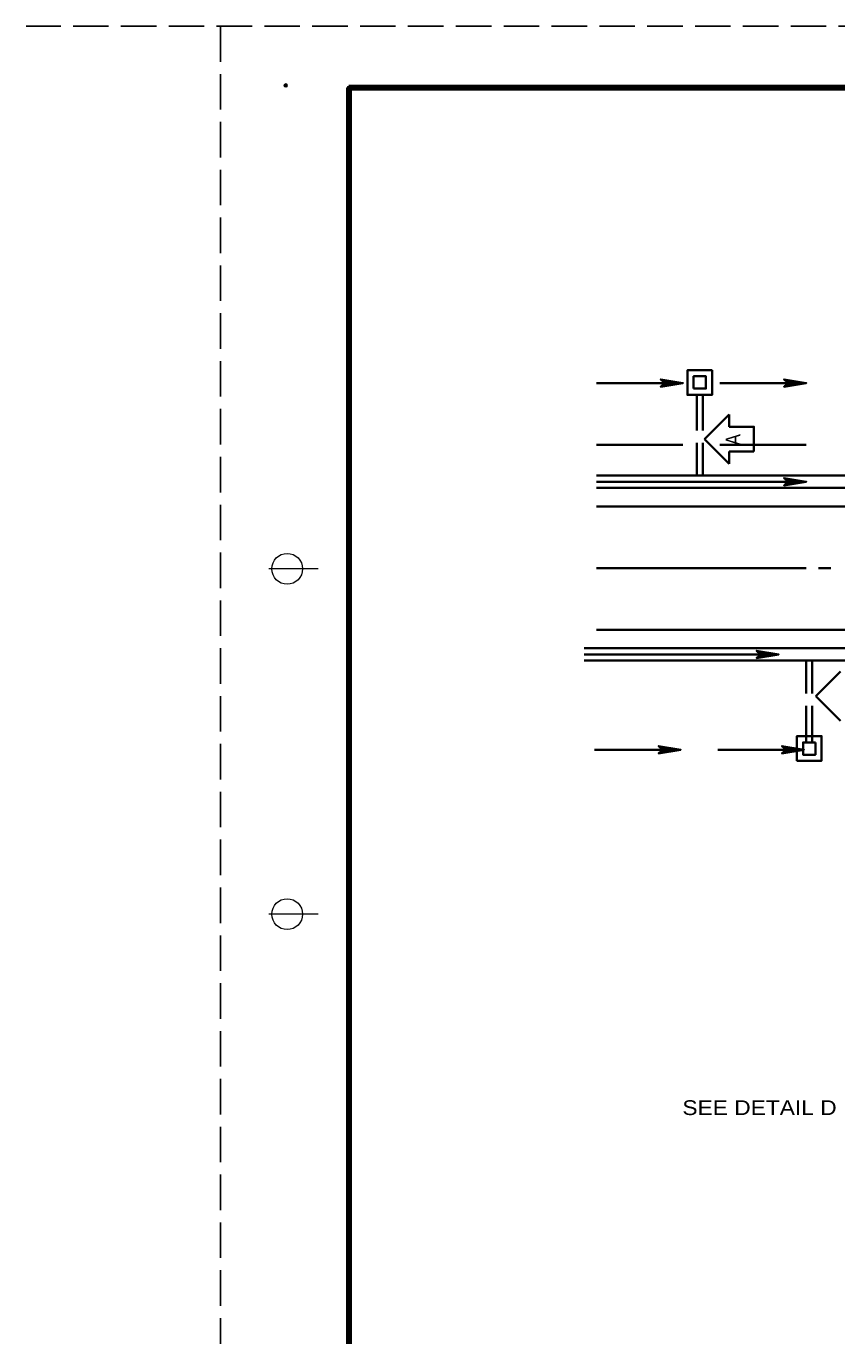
# Model space of a CAD drawing. Extents: x -48732 to -48696.6, y -117659.8 to -117637.8.
# Drawn here: x -48731.96 to -48725.39, y -117648.47 to -117637.85 of the extents above; entities that cross this region are included whole.
import ezdxf

# ---------------------------------------------------------------- set-up
doc = ezdxf.new("R2010")
doc.units = 0
doc.header["$LTSCALE"] = 0.048
doc.header["$PDMODE"] = 32
doc.header["$PDSIZE"] = 0.024
doc.linetypes.add('LONG_DASHED', pattern=[7.5, 6, -1.5])
doc.layers.add('1', color=7, linetype='Continuous', lineweight=25)
doc.layers.add('3', color=7, linetype='Continuous', lineweight=35)

msp = doc.modelspace()

# ---------------------------------------------------------------- linework, layer by layer
at = {"layer": '1', "linetype": 'LONG_DASHED'}
for p, q in [((-48696.76492, -117637.84817), (-48731.96492, -117637.84817)), ((-48730.38992, -117637.84817), (-48730.38992, -117659.84817))]:
    msp.add_line(p, q, dxfattribs=at)
at = {"layer": '1', "lineweight": 158}
for p, q in [((-48729.34825, -117638.34817), (-48729.34825, -117659.34817)), ((-48696.84825, -117638.34817), (-48729.34825, -117638.34817))]:
    msp.add_line(p, q, dxfattribs=at)
at = {"layer": '1', "lineweight": 13}
for p, q in [((-48729.59825, -117642.24817), (-48729.99825, -117642.24817)), ((-48729.59825, -117645.04817), (-48729.99825, -117645.04817))]:
    msp.add_line(p, q, dxfattribs=at)
for centre in [(-48729.84825, -117642.24817), (-48729.84825, -117645.04817)]:
    msp.add_circle(centre, 0.125, dxfattribs=at)
at = {"layer": '1'}
for p in [(-48729.86025, -117638.32817), (-48729.34825, -117638.34817)]:
    msp.add_point(p, dxfattribs=at)
at = {"layer": '3'}
for p, q in [((-48727.33958, -117640.74217), (-48726.63958, -117640.74217)), ((-48726.33958, -117640.74217), (-48725.63958, -117640.74217)), ((-48726.26358, -117640.99617), (-48726.46358, -117641.19617)), ((-48726.26358, -117641.09617), (-48726.26358, -117640.99617)), ((-48726.26358, -117641.39617), (-48726.46358, -117641.19617)), ((-48727.33958, -117641.24217), (-48726.63958, -117641.24217)), ((-48726.33958, -117641.24217), (-48725.63958, -117641.24217)), ((-48726.06358, -117641.29617), (-48726.26358, -117641.29617)), ((-48726.26358, -117641.39617), (-48726.26358, -117641.29617)), ((-48727.33958, -117641.49217), (-48718.76717, -117641.49217)), ((-48727.33958, -117641.54217), (-48725.63958, -117641.54217)), ((-48727.33958, -117641.59217), (-48718.76717, -117641.59217)), ((-48727.33958, -117641.74217), (-48717.32258, -117641.74217)), ((-48727.33958, -117642.24217), (-48725.63958, -117642.24217)), ((-48725.43958, -117642.24217), (-48725.53958, -117642.24217)), ((-48727.33958, -117642.74217), (-48717.32258, -117642.74217)), ((-48727.43958, -117642.89217), (-48718.76717, -117642.89217)), ((-48727.43958, -117642.94217), (-48725.86258, -117642.94217)), ((-48727.43958, -117642.99217), (-48718.76717, -117642.99217)), ((-48725.36258, -117643.08017), (-48725.56258, -117643.28017)), ((-48725.36258, -117643.48017), (-48725.56258, -117643.28017)), ((-48727.35658, -117643.71517), (-48726.65658, -117643.71517)), ((-48726.35658, -117643.71517), (-48725.65658, -117643.71517))]:
    msp.add_line(p, q, dxfattribs=at)
at = {"layer": '3', "linetype": 'LONG_DASHED'}
for p, q in [((-48726.52758, -117640.83817), (-48726.52758, -117641.49217)), ((-48726.47858, -117640.83817), (-48726.47858, -117641.49217)), ((-48725.63958, -117643.64617), (-48725.63958, -117642.99217)), ((-48725.59058, -117643.64617), (-48725.59058, -117642.99217))]:
    msp.add_line(p, q, dxfattribs=at)
at = {"layer": '3'}
for points in [[(-48726.40358, -117640.63817), (-48726.40358, -117640.83817), (-48726.60358, -117640.83817), (-48726.60358, -117640.63817)], [(-48726.55258, -117640.78717), (-48726.55258, -117640.68717), (-48726.45258, -117640.68717), (-48726.45258, -117640.78717)], [(-48725.71458, -117643.80417), (-48725.71458, -117643.60417), (-48725.51458, -117643.60417), (-48725.51458, -117643.80417)], [(-48725.56558, -117643.65517), (-48725.56558, -117643.75517), (-48725.66558, -117643.75517), (-48725.66558, -117643.65517)]]:
    msp.add_lwpolyline(points, close=True, dxfattribs=at)
for points in [[(-48726.81958, -117640.77217), (-48726.63958, -117640.74217), (-48726.81958, -117640.71217), (-48726.81458, -117640.71617), (-48726.65758, -117640.74217), (-48726.81558, -117640.76817), (-48726.81058, -117640.76417), (-48726.67658, -117640.74217), (-48726.81058, -117640.72017), (-48726.80558, -117640.72317), (-48726.69458, -117640.74217), (-48726.80558, -117640.76117), (-48726.80158, -117640.75717), (-48726.71258, -117640.74217), (-48726.80158, -117640.72717), (-48726.79658, -117640.73117), (-48726.73058, -117640.74217), (-48726.79658, -117640.75317), (-48726.79258, -117640.74917), (-48726.74958, -117640.74217), (-48726.79258, -117640.73517), (-48726.78758, -117640.73917), (-48726.76758, -117640.74217), (-48726.78758, -117640.74517), (-48726.81958, -117640.77217), (-48726.78358, -117640.74217), (-48726.81958, -117640.71217)], [(-48725.81958, -117640.77217), (-48725.63958, -117640.74217), (-48725.81958, -117640.71217), (-48725.81458, -117640.71617), (-48725.65758, -117640.74217), (-48725.81558, -117640.76817), (-48725.81058, -117640.76417), (-48725.67658, -117640.74217), (-48725.81058, -117640.72017), (-48725.80558, -117640.72317), (-48725.69458, -117640.74217), (-48725.80558, -117640.76117), (-48725.80158, -117640.75717), (-48725.71258, -117640.74217), (-48725.80158, -117640.72717), (-48725.79658, -117640.73117), (-48725.73058, -117640.74217), (-48725.79658, -117640.75317), (-48725.79258, -117640.74917), (-48725.74958, -117640.74217), (-48725.79258, -117640.73517), (-48725.78758, -117640.73917), (-48725.76758, -117640.74217), (-48725.78758, -117640.74517), (-48725.81958, -117640.77217), (-48725.78358, -117640.74217), (-48725.81958, -117640.71217)], [(-48726.06358, -117641.29617), (-48726.06358, -117641.09617), (-48726.26358, -117641.09617)], [(-48725.81958, -117641.57217), (-48725.63958, -117641.54217), (-48725.81958, -117641.51217), (-48725.81458, -117641.51617), (-48725.65758, -117641.54217), (-48725.81558, -117641.56817), (-48725.81058, -117641.56417), (-48725.67658, -117641.54217), (-48725.81058, -117641.52017), (-48725.80558, -117641.52317), (-48725.69458, -117641.54217), (-48725.80558, -117641.56117), (-48725.80158, -117641.55717), (-48725.71258, -117641.54217), (-48725.80158, -117641.52717), (-48725.79658, -117641.53117), (-48725.73058, -117641.54217), (-48725.79658, -117641.55317), (-48725.79258, -117641.54917), (-48725.74958, -117641.54217), (-48725.79258, -117641.53517), (-48725.78758, -117641.53917), (-48725.76758, -117641.54217), (-48725.78758, -117641.54517), (-48725.81958, -117641.57217), (-48725.78358, -117641.54217), (-48725.81958, -117641.51217)], [(-48726.04258, -117642.97217), (-48725.86258, -117642.94217), (-48726.04258, -117642.91217), (-48726.03758, -117642.91617), (-48725.88058, -117642.94217), (-48726.03858, -117642.96817), (-48726.03358, -117642.96417), (-48725.89958, -117642.94217), (-48726.03358, -117642.92017), (-48726.02858, -117642.92317), (-48725.91758, -117642.94217), (-48726.02858, -117642.96117), (-48726.02458, -117642.95717), (-48725.93558, -117642.94217), (-48726.02458, -117642.92717), (-48726.01958, -117642.93117), (-48725.95358, -117642.94217), (-48726.01958, -117642.95317), (-48726.01558, -117642.94917), (-48725.97258, -117642.94217), (-48726.01558, -117642.93517), (-48726.01058, -117642.93917), (-48725.99058, -117642.94217), (-48726.01058, -117642.94517), (-48726.04258, -117642.97217), (-48726.00658, -117642.94217), (-48726.04258, -117642.91217)], [(-48726.83658, -117643.74517), (-48726.65658, -117643.71517), (-48726.83658, -117643.68517), (-48726.83158, -117643.68917), (-48726.67458, -117643.71517), (-48726.83258, -117643.74117), (-48726.82758, -117643.73717), (-48726.69358, -117643.71517), (-48726.82758, -117643.69317), (-48726.82258, -117643.69617), (-48726.71158, -117643.71517), (-48726.82258, -117643.73417), (-48726.81858, -117643.73017), (-48726.72958, -117643.71517), (-48726.81858, -117643.70017), (-48726.81358, -117643.70417), (-48726.74758, -117643.71517), (-48726.81358, -117643.72617), (-48726.80958, -117643.72217), (-48726.76658, -117643.71517), (-48726.80958, -117643.70817), (-48726.80458, -117643.71217), (-48726.78458, -117643.71517), (-48726.80458, -117643.71817), (-48726.83658, -117643.74517), (-48726.80058, -117643.71517), (-48726.83658, -117643.68517)], [(-48725.83658, -117643.74517), (-48725.65658, -117643.71517), (-48725.83658, -117643.68517), (-48725.83158, -117643.68917), (-48725.67458, -117643.71517), (-48725.83258, -117643.74117), (-48725.82758, -117643.73717), (-48725.69358, -117643.71517), (-48725.82758, -117643.69317), (-48725.82258, -117643.69617), (-48725.71158, -117643.71517), (-48725.82258, -117643.73417), (-48725.81858, -117643.73017), (-48725.72958, -117643.71517), (-48725.81858, -117643.70017), (-48725.81358, -117643.70417), (-48725.74758, -117643.71517), (-48725.81358, -117643.72617), (-48725.80958, -117643.72217), (-48725.76658, -117643.71517), (-48725.80958, -117643.70817), (-48725.80458, -117643.71217), (-48725.78458, -117643.71517), (-48725.80458, -117643.71817), (-48725.83658, -117643.74517), (-48725.80058, -117643.71517), (-48725.83658, -117643.68517)]]:
    msp.add_lwpolyline(points, dxfattribs=at)

# ---------------------------------------------------------------- texts
at = {"layer": '3', "width": 0.85}
msp.add_text('A', height=0.12, rotation=90, dxfattribs=at).set_placement((-48726.17258, -117641.24617))
at = {"layer": '3', "width": 1.15}
msp.add_text('SEE DETAIL D', height=0.12, dxfattribs=at).set_placement((-48726.64383, -117646.67733))

doc.saveas('drawing.dxf')
